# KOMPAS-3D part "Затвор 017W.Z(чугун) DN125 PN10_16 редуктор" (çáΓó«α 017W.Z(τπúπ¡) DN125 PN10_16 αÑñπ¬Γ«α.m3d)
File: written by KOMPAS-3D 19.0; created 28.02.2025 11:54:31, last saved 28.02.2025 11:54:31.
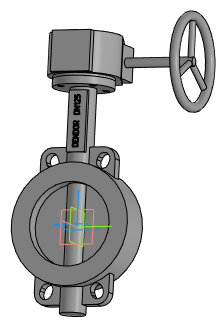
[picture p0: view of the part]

Document properties: Автор: Евгений; Полное имя файла: Затвор 017W.Z(чугун) DN125 PN10_16 редуктор.a3d

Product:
- Part/product: Затвор 017W.Z(чугун) DN125 PN10_16 редуктор
    Масса: 16.0918

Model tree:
1. Операция без истории:1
